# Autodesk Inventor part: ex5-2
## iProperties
Author: Administrator
Created: 2001-09
Part Number: ex5-2
Document SubType Name: Modeling
Designer: Administrator
Control State: 0
Master: False
Checked Out: False
PropertySet Name: Design Tracking Control
Length Units: 11272
Angle Units: 11279
Time Units: 11290
Mass Units: 11286
Shininess: 3
Angle Display Precision: 2
Document Length Units: 11272
Document Angle Units: 11286
Document Time Units: 11279
Document Mass Units: 11290
Document Length Units Precision: 3
Document Angle Units Precision: 2
Compacted: False
PropertySet Name: _Private Model Information
Density: 0.0
Volumn: 0.0
Area: 0.0
PropertySet Name: Model Information
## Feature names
1. Revolution1
2. Hole1
